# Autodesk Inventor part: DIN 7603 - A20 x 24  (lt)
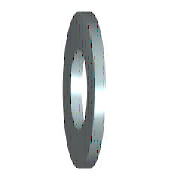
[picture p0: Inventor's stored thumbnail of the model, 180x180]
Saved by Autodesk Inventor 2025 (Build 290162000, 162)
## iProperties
Created: 2024-01
Part Number: DIN 7603 - A20 x 24  (lt)
Material: Acciaio, Dolce
Description: Guarnizione ad anello
Document SubType Name: Modeling
Standard: DIN 7603
Designer: R5800u
Standards Organization: DIN
Language: it-IT
Size Designation: A20 x 24  (lt)
Categories: <MemberInstance><Categories><Category DisplayName="Altre parti" InternalName="5aa15e00-363f-49f2-933f-16f664388e3f" Mnemonic="OTHER"><Category DisplayName="Anel
Density: 7.85 g/cm^3
Appearance: Semilucidato
IsCustomPart: 0
Author: R5800u
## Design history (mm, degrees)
body "Solid1"
sketch "Schizzo"
  geometry: C1 r 11.95 at (0, 0); C2 r 10.1 at (0, 0); 1 further point
  constraints: 2 centre point, 2 coincident
  dimensions: "d0" = 20.2 diameter of C2 (= SD1); "d1" = 23.9 diameter of C1 (= SD2)
extrude "Corpo" new body sketch "Schizzo" distance "d2" = 1.5 (= SD); taper "d3" = 0 deg
workaxis "Work Axis1"
workplane "Work Plane1"
other parameters: "SD1" = 20.2 [user parameter; used in 1 equation term], "SD2" = 23.9 [user parameter; used in 1 equation term], "SD" = 1.5 [user parameter; used in 1 equation term], "d4" = 0, "d5" = 0, "d6" = 0, "d7" = 0
